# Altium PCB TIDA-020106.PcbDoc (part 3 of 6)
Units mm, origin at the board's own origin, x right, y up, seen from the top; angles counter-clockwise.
Board outline 158.53 x 83.25 mm, 6 copper layers (Top Layer, GND, Power, Sig4, GND (Mid4), Bottom Layer), stack 1.59 mm thick; 410 components, 255 nets, 1280 pads, 2405 vias.
Unrouted connection lines stored in the file: 294.
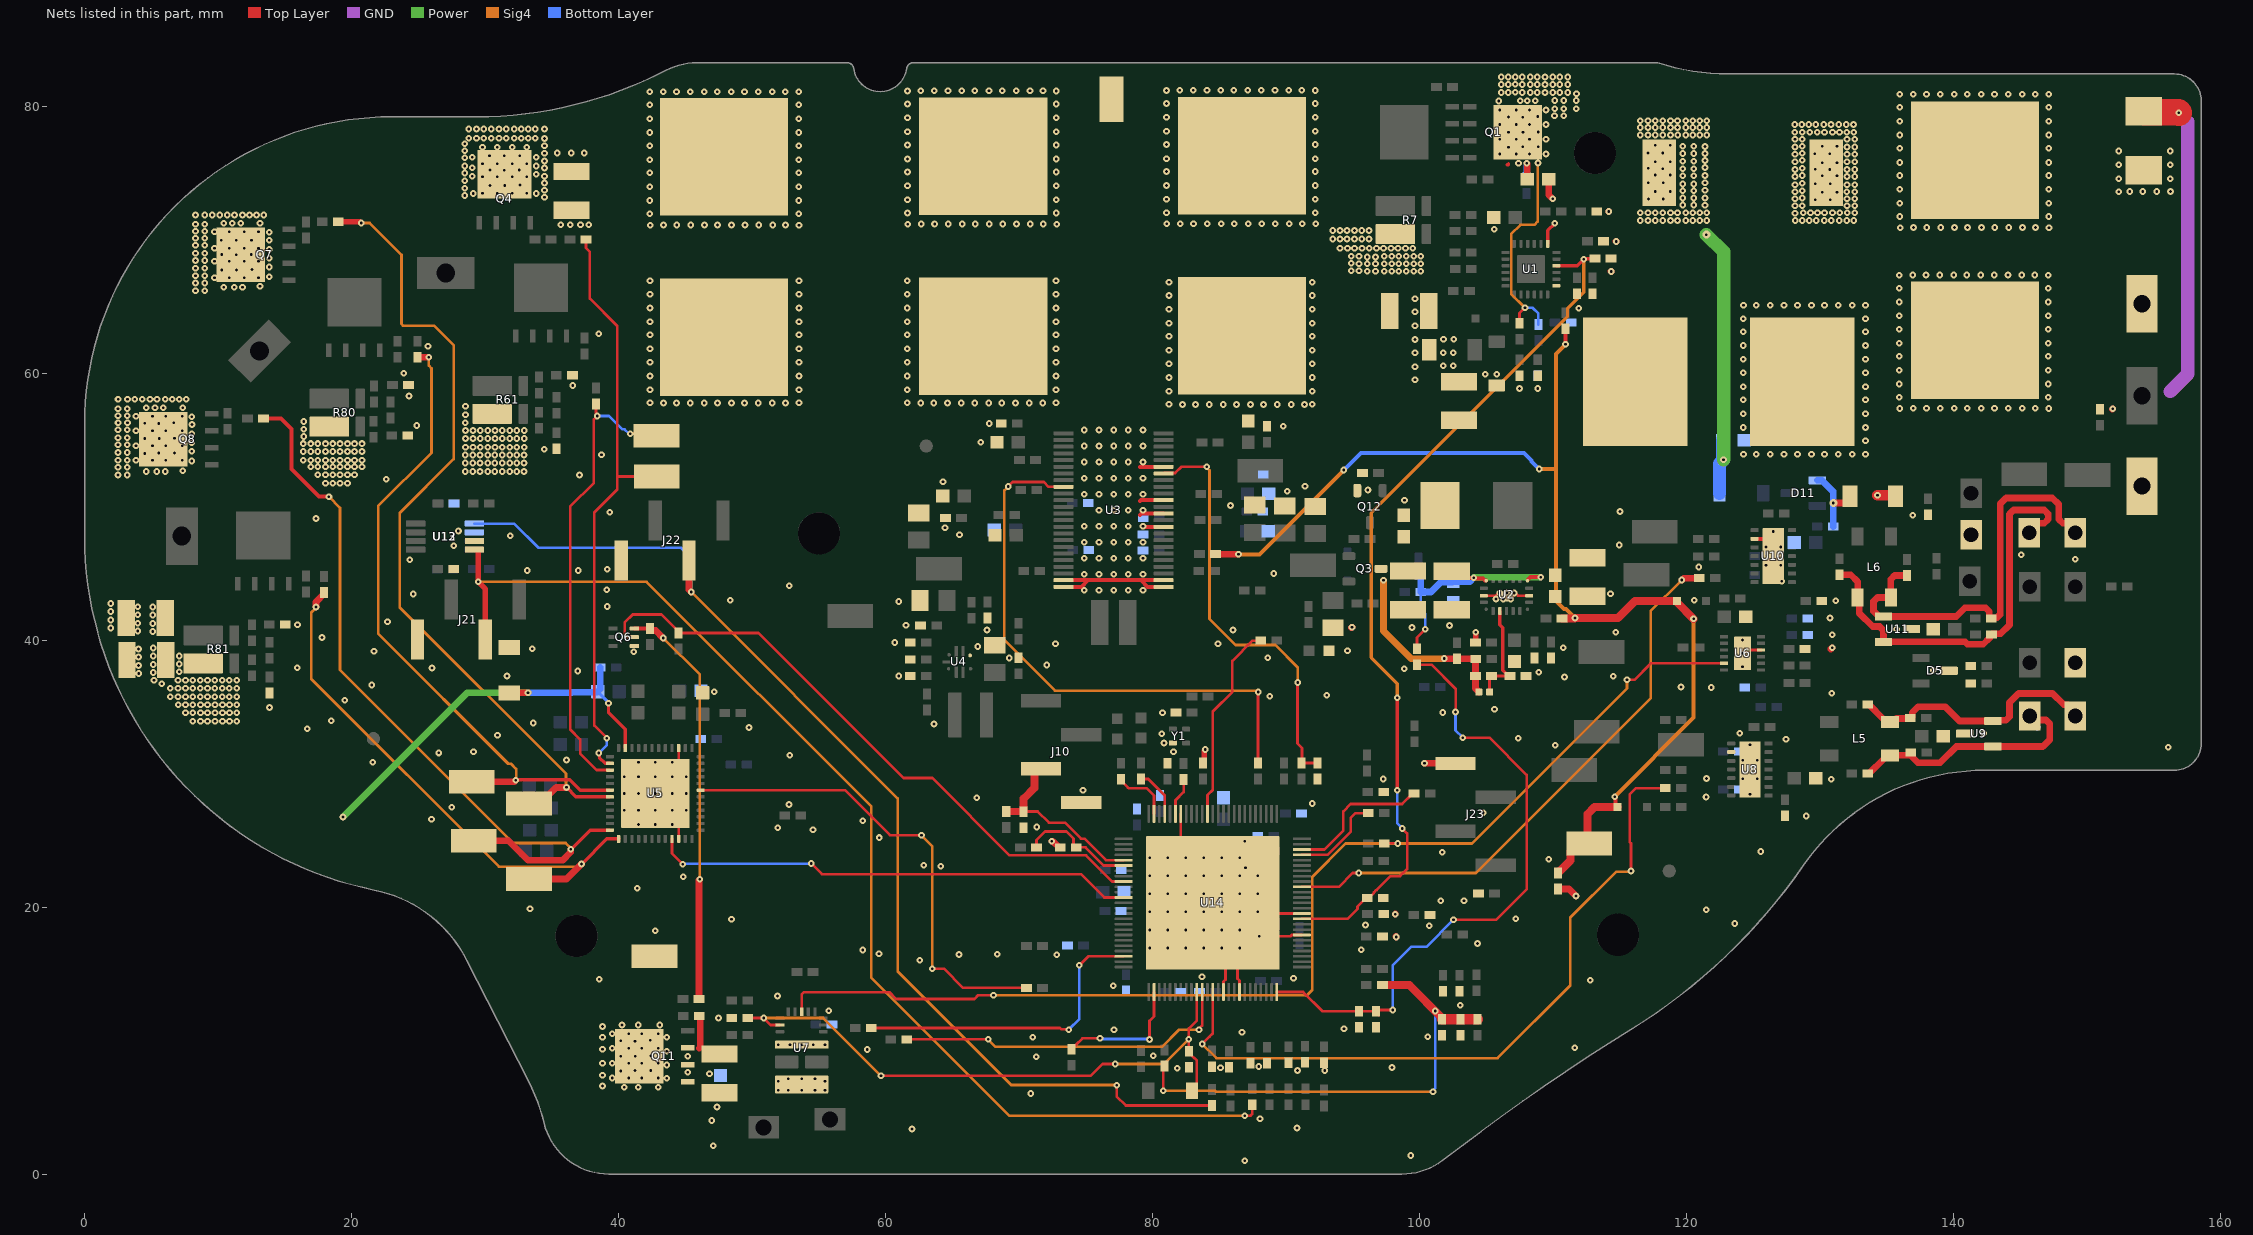
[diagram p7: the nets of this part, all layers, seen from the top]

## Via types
v1: diameter 0.5, hole 0.2, Top Layer to Bottom Layer, 2315 vias
v2: diameter 0.5, hole 0.2, Top Layer to Bottom Layer, tented both sides, 87 vias
v3: diameter 0.6, hole 0.2, Top Layer to Bottom Layer, 3 vias

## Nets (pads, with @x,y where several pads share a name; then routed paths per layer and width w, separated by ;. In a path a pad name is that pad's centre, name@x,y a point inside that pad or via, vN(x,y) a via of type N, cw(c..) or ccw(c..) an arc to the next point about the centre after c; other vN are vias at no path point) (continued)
12V_Cobra: C25.1 C26.2 C30.2 L2.2 Q3.3 R25.2 R32.1 R33.1 | length 13.9
  Top Layer w0.5: v1(101.831,38.624) 101.854,38.601 R32.1@104.019,38.601 ; R32.1@104.182,38.567 104.182,37.32 R33.1@104.177,37.316 104.177,36.37 C30.2@104.432,36.114
  Sig4 w0.5: v1(97.285,44.485) 97.285,40.687 99.349,38.624 ; 99.365,38.607 101.815,38.607 v1(101.831,38.624)
48V/12V_BDC: C96.2 C97.1 Q11.1 Q11.2 Q11.3 R87.1 U7.4 | length 2.5
  Top Layer w0.5: R87.1@46.026,11.849 46.063,11.849 46.113,11.799 46.113,9.508 46.041,9.436
  Bottom Layer w0.2: v1@45.156,7.624 45.158,7.624 v1(45.163,7.628)
  other v1: 45.163,8.83
  other v2: 51.96,9.695 52.835,9.695 53.71,9.695 54.585,9.695 55.46,9.695
48V/12V_C: C16.1 D11.1 R99.2 | length 5.8
  Top Layer w0.5: v3(130.984,50.265) 131.936,50.265 132.236,50.565 C16.1@132.236,50.781 C16.1@132.218,50.799
  Bottom Layer w0.5: D11.1@129.781,51.964 130.131,51.964 130.965,51.13 130.965,50.284 v3(130.984,50.265) 130.984,48.502 R99.2@130.983,48.501
48V/12V_IN: C8.1 D1.2 J3.1 L1.1
  other v1: 135.985,70.892 147.138,70.892 136.985,70.908 137.985,70.908 139.02,70.908 140.058,70.908 141.029,70.908 142.085,70.908 143.085,70.908 144.12,70.908 145.158,70.908 146.129,70.908 128.124,71.433 128.651,71.433 129.18,71.436 129.703,71.433 130.307,71.433 130.838,71.433 131.414,71.433 131.982,71.433 132.523,71.433 135.957,71.733 147.109,71.733 128.117,71.986 128.74,72.003 129.267,72.003 129.797,72.005 130.32,72.003 130.924,72.003 131.455,72.003 132.03,72.003 132.599,72.003 128.11,72.54 128.65,72.543 132,72.54 132.599,72.54 135.957,72.733 147.109,72.733 129.633,72.975 130.739,72.975 128.11,73.067 132,73.067 132.599,73.067 128.65,73.122 130.153,73.546 131.258,73.546 128.107,73.596 131.997,73.596 132.596,73.596 152.356,73.594 153.19,73.6 154.162,73.6 155.2,73.6 156.235,73.6 128.65,73.662 135.957,73.768 147.109,73.768 128.11,74.119 132,74.119 132.599,74.119 129.626,74.186 130.739,74.186 128.65,74.231 152.356,74.562 156.223,74.565 128.11,74.723 132,74.723 132.599,74.723 128.65,74.806 130.153,74.783 131.258,74.783 135.957,74.806 147.109,74.806 128.11,75.254 130.705,75.254 132,75.254 132.599,75.254 129.626,75.273 128.65,75.337 152.356,75.6 156.223,75.6 130.153,75.767 131.258,75.767 135.957,75.778 147.109,75.778 128.11,75.83 132,75.83 132.599,75.83 128.65,75.941 128.11,76.398 132,76.398 132.599,76.398 129.601,76.42 130.705,76.42 128.653,76.464 152.356,76.635 156.223,76.638 135.957,76.833 147.109,76.833 128.11,76.938 132,76.938 132.599,76.938 128.65,76.994 130.153,77.003 131.258,77.003 128.11,77.517 128.65,77.521 132,77.517 132.599,77.517 135.957,77.833 147.109,77.833 128.104,78.041 128.645,78.041 129.213,78.041 129.789,78.041 130.32,78.041 130.924,78.041 131.447,78.038 131.976,78.041 132.503,78.041 128.093,78.623 128.62,78.623 129.149,78.626 129.672,78.623 130.277,78.623 130.808,78.623 131.383,78.623 131.951,78.623 132.492,78.623 135.957,78.868 147.109,78.868 135.957,79.906 147.109,79.906 135.957,80.878 147.109,80.878 136.957,80.894 137.957,80.894 138.992,80.894 140.029,80.894 141.001,80.894 142.057,80.894 143.057,80.894 144.092,80.894 145.129,80.894 146.101,80.894
48V/12V_IN_FILTERED: C9.2 C10.2 D3.2 L1.2 Q1.5 R12.2 R13.2 R153.1 | length 40.3
  Top Layer w0.2: R12.2@107.48,63.736 107.48,64.496 v1(107.881,64.896)
  Top Layer w0.25: 106.554,75.614 106.632,75.614 106.654,75.635 106.654,75.706
  Top Layer w0.5: v1(108.013,75.721) 108.059,75.676 C10.2@108.059,74.515
  Top Layer w1: Q1.5@107.281,77.863 Q1.5@107.459,78.041
  Power w1: v3(121.473,70.374) 122.768,69.079 122.768,53.529 v1(122.753,53.514)
  Sig4 w0.2: v1(107.881,64.896) 106.852,65.925 106.852,70.419 107.541,71.108 108.599,71.108 108.84,71.349 108.84,75.719 v1(108.859,75.738)
  Bottom Layer w0.2: v1(107.881,64.896) 108.454,64.896 108.886,64.465 R13.2@108.886,63.641
  Bottom Layer w0.5: R153.1@108.013,74.659 R153.1@108.013,74.808 ; R153.1@108.013,74.809 v1(108.013,75.721)
  Bottom Layer w1: D3.2@122.454,50.999 122.454,53.215 v1(122.753,53.514) 122.712,53.555 C9.2@122.712,54.963
  other v1: 116.52,71.433 117.099,71.433 117.639,71.433 118.208,71.433 118.783,71.433 119.314,71.433 119.918,71.433 120.441,71.43 120.971,71.433 121.498,71.433 116.52,72.005 117.099,72.005 117.639,72.005 118.208,72.005 118.783,72.005 119.314,72.005 119.918,72.005 120.441,72.003 120.971,72.005 121.498,72.005 119.7,72.591 120.523,72.591 121.369,72.581 117.135,73.037 118.242,73.037 119.7,73.118 120.523,73.118 121.369,73.122 117.656,73.608 118.761,73.608 119.697,73.648 120.52,73.648 121.369,73.69 119.7,74.171 120.523,74.171 117.129,74.249 118.242,74.249 121.369,74.266 119.7,74.775 120.523,74.775 121.369,74.797 117.656,74.845 118.761,74.845 119.7,75.306 120.523,75.306 117.129,75.335 118.208,75.316 121.369,75.401 107.4,75.731 117.656,75.829 118.761,75.829 119.7,75.881 120.523,75.881 121.372,75.924 106.004,76.406 107.241,76.406 108.225,76.406 109.462,76.406 119.7,76.45 120.523,76.45 121.369,76.453 117.103,76.482 118.208,76.482 106.645,76.925 107.713,76.959 108.878,76.959 119.7,76.99 120.523,76.99 121.369,76.98 117.656,77.066 118.761,77.066 106.004,77.511 107.241,77.511 108.225,77.511 109.462,77.511 116.527,77.833 117.106,77.833 117.646,77.833 118.215,77.833 118.79,77.833 119.321,77.833 119.925,77.833 120.448,77.83 120.978,77.833 121.505,77.833 106.645,78.038 107.731,78.038 108.878,78.064 116.52,78.399 117.099,78.399 117.639,78.399 118.208,78.399 118.783,78.399 119.314,78.399 119.918,78.399 120.441,78.396 120.971,78.399 121.498,78.399 106.004,78.628 107.241,78.628 108.225,78.628 109.462,78.628 116.52,78.913 117.099,78.913 117.639,78.913 118.208,78.913 118.783,78.913 119.314,78.913 119.918,78.913 120.441,78.91 120.971,78.913 121.498,78.913 107.713,79.164 106.645,79.182 108.84,79.217 110.102,79.287 110.792,79.287 106.004,79.706 107.241,79.706 108.225,79.706 109.462,79.706 110.105,79.809 110.795,79.809 111.736,79.809 105.927,80.388 107.536,80.409 108.059,80.406 108.663,80.406 110.105,80.414 110.795,80.414 111.736,80.414 111.739,80.937 106.1,81.024 106.627,81.024 107.157,81.027 107.679,81.024 108.284,81.024 108.815,81.024 109.39,81.024 109.958,81.024 110.499,81.024 111.077,81.024 106.1,81.623 106.627,81.623 107.157,81.626 107.679,81.623 108.284,81.623 108.815,81.623 109.39,81.623 109.958,81.623 110.499,81.623 111.077,81.623 106.1,82.179 106.627,82.179 107.157,82.181 107.679,82.179 108.284,82.179 108.815,82.179 109.39,82.179 109.958,82.179 110.499,82.179 111.077,82.179
48V/12V_P: C5.1 C6.1 C21.1 C22.1 C23.2 C24.2 C28.1 C60.1 C61.1 C67.2 C68.1 C73.1 C74.1 C75.1 C76.1 Q4.5 Q7.5 Q8.5 Q11.5 R7.1 R22.2 R27.1 R58.2 R127.2 TP1.1 U2.11 U2.17 U5.35 | length 50.7
  Top Layer w0.2: R127.2@99.798,39.359 99.798,40.195 v1(100.42,40.817)
  Top Layer w0.25: v1(39.233,35.268) 39.233,34.589 40.493,33.329 U5.35@40.493,31.915
  Top Layer w0.3: C22.1@102.402,45.165 102.9,44.667 v1(104.038,44.667) 104.076,44.629 104.73,44.629 104.909,44.45 U2.17@104.983,44.45 ; 108.158,44.587 108.286,44.715 v1(109.061,44.715)
  Top Layer w0.5: C68.1@31.813,36.063 v1(33.213,36.063)
  Power w0.5: v1(19.351,26.751) 28.663,36.063 v1(33.213,36.063) ; v1(104.038,44.667) 104.086,44.715 v1(109.061,44.715)
  Bottom Layer w0.2: R22.2@100.078,43.601 100.078,42.28 100.42,41.938 v1(100.42,40.817)
  Bottom Layer w0.25: C67.2@38.433,36.143 39.185,35.391 39.185,35.316 v1(39.233,35.268)
  Bottom Layer w0.5: v1(33.213,36.063) 36.484,36.063 36.524,36.103 38.393,36.103 C67.2@38.433,36.143 38.612,36.322 R58.2@38.612,37.959 ; R27.1@99.9,44.914 99.9,44.855 100.078,44.677 R22.2@100.078,43.601 100.852,43.601 101.591,44.339 102.441,44.339 102.467,44.366 103.737,44.366 v1(104.038,44.667)
  other v1: 40.421,6.505 41.456,6.505 42.96,6.504 38.788,6.599 43.593,7.178 39.516,7.205 40.753,7.205 41.737,7.205 42.974,7.205 38.788,7.41 40.157,7.724 41.225,7.758 42.391,7.758 43.593,8.178 38.788,8.31 39.516,8.31 40.753,8.31 41.737,8.31 42.974,8.31 40.157,8.837 41.243,8.837 42.391,8.863 43.593,9.213 38.788,9.345 39.516,9.428 40.753,9.428 41.737,9.428 42.974,9.428 40.157,9.981 41.225,9.963 42.352,10.016 38.788,10.251 43.593,10.251 39.516,10.505 40.753,10.505 41.737,10.505 42.974,10.505 38.788,11.061 40.249,11.164 41.456,11.164 43.068,11.17 4.046,37.499 4.035,38.095 4.035,38.733 4.035,39.332 3.987,40.677 1.957,40.91 3.976,41.273 1.946,41.506 3.976,41.911 1.946,42.144 3.976,42.51 1.946,42.743 2.5,52.365 3.2,52.365 4.616,52.627 5.396,52.627 6.028,52.627 7.335,52.693 2.5,52.944 3.2,52.944 8.022,53.417 3.849,53.465 5.086,53.465 6.07,53.465 7.306,53.465 2.5,53.484 3.2,53.484 4.489,53.984 5.557,54.017 6.723,54.017 2.5,54.052 3.2,54.052 8.022,54.139 3.849,54.57 5.086,54.57 6.07,54.57 7.306,54.57 2.5,54.628 3.2,54.628 8.022,54.789 4.489,55.096 5.576,55.096 6.723,55.122 2.5,55.159 3.2,55.159 8.022,55.452 3.849,55.687 5.086,55.687 6.07,55.687 7.306,55.687 2.5,55.763 3.2,55.763 8.034,56.145 5.557,56.222 4.489,56.241 2.503,56.286 3.203,56.286 6.684,56.275 8.022,56.741 3.849,56.765 5.086,56.765 6.07,56.765 7.306,56.765 2.5,56.815 3.2,56.815 2.5,57.342 3.2,57.342 4.616,57.403 5.885,57.403 7.335,57.403 5.266,57.412 2.503,58.03 3.208,58.033 3.748,58.033 4.317,58.033 4.892,58.033 5.423,58.033 6.028,58.033 6.55,58.03 7.08,58.033 7.607,58.033 8.296,66.177 8.996,66.177 10.412,66.439 11.193,66.439 11.824,66.439 13.131,66.504 8.296,66.755 8.996,66.755 9.72,67.141 10.825,67.141 11.942,67.141 13.02,67.141 13.818,67.229 8.296,67.295 8.996,67.295 96.073,67.625 96.688,67.625 97.35,67.631 97.907,67.631 98.428,67.631 98.992,67.631 99.545,67.631 100.079,67.631 94.875,67.668 95.451,67.658 10.273,67.725 11.377,67.725 12.53,67.763 8.296,67.864 8.996,67.864 13.818,67.951 95.451,68.193 96.073,68.182 96.688,68.182 97.35,68.191 97.907,68.191 98.428,68.191 98.992,68.191 99.545,68.191 100.079,68.191 94.875,68.225 9.72,68.378 10.825,68.378 11.942,68.378 13.02,68.378 8.296,68.439 8.996,68.439 13.818,68.601 96.073,68.703 96.688,68.703 94.875,68.745 95.451,68.745 97.35,68.745 97.907,68.745 98.428,68.745 98.992,68.745 99.545,68.745 100.079,68.745 11.351,68.872 10.273,68.89 12.477,68.89 8.296,68.97 8.996,68.97 13.818,69.264 9.72,69.362 10.825,69.362 11.942,69.362 13.02,69.362 94.032,69.355 94.589,69.355 95.11,69.355 95.674,69.355 96.227,69.355 96.761,69.355 97.293,69.355 97.85,69.355 98.371,69.355 98.935,69.355 99.488,69.355 8.296,69.575 8.996,69.575 10.239,69.958 11.351,69.958 12.496,69.958 13.83,69.957 93.475,70.048 94.032,70.048 94.552,70.048 95.117,70.048 95.67,70.048 96.204,70.048 8.299,70.097 8.999,70.097 13.818,70.553 9.72,70.599 10.825,70.599 11.942,70.599 13.02,70.599 8.296,70.627 8.996,70.627 93.475,70.686 94.032,70.686 94.552,70.686 95.117,70.686 95.67,70.686 96.204,70.686 42.355,71.084 53.508,71.084 43.355,71.1 44.355,71.1 45.39,71.1 46.428,71.1 47.4,71.1 48.455,71.1 49.455,71.1 50.49,71.1 51.528,71.1 52.5,71.1 61.662,71.148 72.815,71.148 8.296,71.154 8.996,71.154 62.662,71.164 63.662,71.164 64.697,71.164 65.735,71.164 66.707,71.164 67.762,71.164 68.762,71.164 69.797,71.164 70.835,71.164 71.807,71.164 81.057,71.183 82.057,71.199 83.057,71.199 84.092,71.199 85.129,71.199 86.101,71.199 87.157,71.199 88.157,71.199 89.192,71.199 90.229,71.199 91.201,71.199 92.209,71.183 10.412,71.215 11.063,71.223 11.681,71.215 13.131,71.215 8.299,71.842 9.004,71.845 9.545,71.845 10.113,71.845 10.689,71.845 11.22,71.845 11.824,71.845 12.347,71.842 12.876,71.845 13.403,71.845 42.327,71.925 53.48,71.925 61.634,71.989 72.787,71.989 81.029,72.024 92.181,72.024 42.327,72.925 53.48,72.925 61.634,72.989 72.787,72.989 81.029,73.024 92.181,73.024 34.443,73.178 28.471,73.303 29.103,73.45 33.813,73.45 29.803,73.469 30.908,73.469 32.026,73.469 33.103,73.469 34.443,73.705 28.471,73.843 42.327,73.96 53.48,73.96 61.634,74.024 72.787,74.024 30.356,74.053 31.461,74.053 81.029,74.059 92.181,74.059 32.614,74.091 34.44,74.234 28.471,74.412 29.803,74.706 30.908,74.706 32.026,74.706 33.103,74.706 29.037,74.757 34.443,74.757 33.813,74.9 28.471,74.987 42.327,74.998 53.48,74.998 61.634,75.062 72.787,75.062 81.029,75.096 92.181,75.096 31.435,75.2 30.356,75.219 32.561,75.219 34.443,75.361 29.037,75.388 28.471,75.518 33.822,75.518 29.803,75.69 30.908,75.69 32.026,75.69 33.103,75.69 34.443,75.892 42.327,75.97 53.48,75.97 61.634,76.034 72.787,76.034 81.029,76.068 92.181,76.068 28.471,76.122 29.037,76.169 33.813,76.169 30.322,76.286 31.435,76.286 32.579,76.286 34.443,76.468 35.402,76.489 36.457,76.489 37.429,76.489 28.474,76.645 29.803,76.927 30.908,76.927 32.026,76.927 33.103,76.927 34.443,77.036 42.327,77.025 53.48,77.025 61.634,77.089 72.787,77.089 81.029,77.124 92.181,77.124 28.471,77.175 28.775,77.585 29.354,77.585 29.894,77.585 30.462,77.585 31.038,77.585 31.569,77.585 32.173,77.585 32.696,77.582 33.225,77.585 33.752,77.585 34.443,77.577 42.327,78.025 53.48,78.025 61.634,78.089 72.787,78.089 81.029,78.124 92.181,78.124 28.775,78.285 29.354,78.285 29.894,78.285 30.462,78.285 31.038,78.285 31.569,78.285 32.173,78.285 32.696,78.282 33.225,78.285 33.752,78.285 34.44,78.282 42.327,79.06 53.48,79.06 61.634,79.124 72.787,79.124 81.029,79.159 92.181,79.159 42.327,80.098 53.48,80.098 61.634,80.162 72.787,80.162 81.029,80.196 92.181,80.196 42.327,81.07 53.48,81.07 43.327,81.086 44.327,81.086 45.362,81.086 46.4,81.086 47.372,81.086 48.427,81.086 49.427,81.086 50.462,81.086 51.5,81.086 52.472,81.086 61.634,81.134 62.634,81.15 63.634,81.15 64.669,81.15 65.707,81.15 66.679,81.15 67.734,81.15 68.734,81.15 69.769,81.15 70.807,81.15 71.779,81.15 72.787,81.134 81.029,81.168 92.181,81.168 82.029,81.184 83.029,81.184 84.064,81.184 85.101,81.184 86.073,81.184 87.129,81.184 88.129,81.184 89.164,81.184 90.201,81.184 91.173,81.184
BOOT1: J10.3 R147.2 R149.2 U14.80 | length 13.9
  Top Layer w0.2: R149.2@70.336,27.162 71.379,27.162 72.219,26.322 73.44,26.322 74.634,25.128 74.886,25.128 76.497,23.517 U14.80@77.827,23.517
  Top Layer w0.5: R147.2@69.031,27.162 69.035,27.157 70.331,27.157 R149.2@70.336,27.153
  Top Layer w0.6: R149.2@70.336,27.162 70.336,28.122 71.149,28.935 J10.3@71.149,30.375
BOOT2: R148.2 R150.2 U14.81 | length 8.7
  Top Layer w0.2: R148.2@71.295,24.482 71.295,25.029 71.931,25.665 73.531,25.665 74.068,25.128 74.068,24.682 R150.2@74.269,24.482 ; R150.2@74.269,24.482 74.966,24.482 76.331,23.117 U14.81@77.827,23.117
CAN1H: J17.1 L5.2 R98.1 R100.2 U9.2 | length 19.9
  Top Layer w0.5: R98.1@133.551,35.17 133.651,35.17 134.756,34.065 135.026,34.065 L5.2@135.226,33.865 135.451,33.865 135.716,34.13 136.697,34.13 R100.2@136.747,34.18 136.847,34.18 136.897,34.23 136.897,34.57 137.344,35.017 139.353,35.017 140.433,33.937 U9.2@142.933,33.937 142.983,33.987 143.901,33.987 144.175,34.262 144.175,35.323 144.859,36.007 147.404,36.007 148.25,35.161 148.55,35.161 149.1,34.611 J17.1@149.1,34.311 ; J17.1@149.2,34.011 J17.1@149.2,34.311
CAN1L: J18.1 L5.1 R103.1 R105.1 U9.1 | length 19.3
  Top Layer w0.5: R105.1@133.551,29.997 133.651,29.997 134.801,31.147 134.801,31.165 135.001,31.365 L5.1@135.226,31.365 R103.1@136.876,31.365 ; R103.1@136.876,31.515 136.926,31.515 136.926,31.201 137.312,30.815 138.975,30.815 140.197,32.037 U9.1@142.933,32.037 146.679,32.037 147.2,32.558 147.2,33.73 146.907,34.023 J18.1@145.7,34.023
  Bottom Layer w0.5: J18.1@145.7,34.311 145.7,34.011 J18.1@146.25,33.461
CAN2H: J19.1 L6.2 R109.1 R110.2 U11.1 | length 31.6
  Top Layer w0.5: R109.1@136.492,44.84 135.577,44.84 135.284,44.547 135.284,43.211 L6.2@135.301,43.193 134.285,43.193 133.992,42.901 133.992,42.167 134.392,41.767 U11.1@134.742,41.767 140.188,41.767 140.841,42.421 142.375,42.421 142.668,42.128 142.668,41.684 142.718,41.634 R110.2@142.818,41.634 142.868,41.684 143.253,41.684 143.475,41.906 143.475,50.199 143.924,50.648 147.381,50.648 147.875,50.153 147.875,49.043 148.168,48.75 148.65,48.75 149.2,48.2 J19.1@149.2,47.9
CAN2L: J20.1 L6.1 R113.1 R115.1 U11.2 | length 31.3
  Top Layer w0.5: R115.1@131.455,44.892 132.291,44.892 132.801,44.382 L6.1@132.801,43.193 132.919,43.076 132.919,42.034 133.936,41.017 134.449,41.017 134.742,40.724 U11.2@134.742,39.867 140.858,39.867 141.039,39.686 142.211,39.686 142.675,40.15 142.675,40.386 142.725,40.436 R113.1@142.825,40.436 142.875,40.486 143.525,40.486 144.175,41.136 144.175,49.439 144.486,49.75 146.777,49.75 147.071,49.457 147.071,49.043 146.778,48.75 146.3,48.75 145.75,48.2 J20.1@145.75,47.9
CLK_DRV3263: R143.1 U5.19 | length 35.9
  Top Layer w0.2: U5.19@46.143,28.765 56.949,28.765 60.323,25.391 v1(62.676,25.391) ; v1(63.495,15.392) 64.352,15.392 65.785,13.958 R143.1@70.549,13.958
  Sig4 w0.2: v1(62.676,25.391) 62.676,25.347 63.495,24.528 v1(63.495,15.392)
CLK_PMIC: R142.2 U3.33 | length 42.1
  Top Layer w0.2: v1(69.173,51.502) 69.512,51.84 71.854,51.84 72.208,51.485 U3.33@73.324,51.485 ; R142.2@87.882,30.797 87.882,36.194 v1@87.902,36.214
  Sig4 w0.2: v1(69.173,51.502) 68.884,51.212 68.884,40.014 72.683,36.214 v1@87.902,36.214
  other v1: 87.902,36.114
CLKEPB: R135.1 U6.11 U7.13 | length 87.4
  Top Layer w0.2: U7.13@53.71,12.17 53.71,13.465 53.876,13.631 60.268,13.631 60.777,13.122 66.636,13.122 66.914,13.399 v1(68.08,13.399) ; R135.1@97.35,24.782 98.338,24.782 v1(98.355,24.765) ; v1(115.521,37.029) 116.076,37.029 117.306,38.259 U6.11@122.791,38.259
  Sig4 w0.2: v1(68.08,13.399) 91.571,13.399 91.952,13.781 91.952,22.273 94.445,24.765 v1(98.355,24.765) 103.9,24.765 115.521,36.386 v1(115.521,37.029)
COS_P1: J21.2 R121.1 U12.1 | length 90
  Top Layer w0.2: v1(86.899,4.365) 86.917,4.383 87.34,4.383 87.457,4.5 R121.1@87.457,5.2
  Top Layer w0.4: U12.1@29.2,46.775 29.465,46.775 29.49,46.75 v1(29.49,44.369) 29.49,44.342 30.01,43.822 J21.2@30.01,40.043
  Sig4 w0.2: v1(29.49,44.369) 42.095,44.369 58.92,27.544 58.92,14.703 69.258,4.365 v1(86.899,4.365)
COS_P2: J22.2 R125.1 U13.1 | length 85.3
  Top Layer w0.2: v1(77.301,6.654) 77.301,5.828 77.984,5.145 R125.1@84.456,5.145
  Top Layer w0.5: J22.2@45.272,45.963 45.272,43.771 v1(45.441,43.603)
  Sig4 w0.2: v1(45.441,43.603) 60.892,28.152 60.892,15.196 69.406,6.682 77.273,6.682 v1(77.301,6.654)
  Bottom Layer w0.2: U13.1@29.189,48.727 32.17,48.727 33.977,46.919 44.664,46.919 45.441,46.143 v1(45.441,43.603)
CUTOFF_ASCIN: Q6.2 R53.1 U14.84 | length 47.7
  Top Layer w0.2: Q6.2@41.175,40.216 40.611,40.216 40.45,40.377 40.45,41.316 41.054,41.92 43.212,41.92 44.494,40.638 R53.1@44.494,40.538 50.465,40.538 61.328,29.675 63.495,29.675 69.288,23.882 75,23.882 76.965,21.917 U14.84@77.827,21.917
Cutoff_EPB: Q6.3 R57.1 R85.1 | length 30.7
  Top Layer w0.3: Q6.3@41.175,40.866 R57.1@42.34,40.866
  Top Layer w0.5: R57.1@42.34,40.866 42.34,40.766 42.39,40.716 42.772,40.716 v1(43.329,40.159) ; R85.1@46.018,13.122 46.018,22.02 v1(46.077,22.079)
  Sig4 w0.2: v1(43.329,40.159) 46.077,37.412 v1(46.077,22.079)
DC_BUS: C115.1 R127.1 R132.2 U14.25 | length 47.4
  Top Layer w0.2: U14.25@89.302,13.642 91.267,13.642 92.709,12.2 C115.1@95.449,12.2 R132.2@96.739,12.2 ; R132.2@96.939,11.9 96.739,12.1 96.936,12.297 v1(97.969,12.297) ; R127.1@99.798,38.159 100.893,38.159 102.694,36.357 102.694,34.616 v1(102.687,34.609) ; v1(102.536,19.057) 105.741,19.057 108.015,21.332 108.015,29.91 105.232,32.693 v1(103.227,32.693)
  Bottom Layer w0.2: v1(97.969,12.297) 97.969,15.633 99.365,17.03 100.508,17.03 v1(102.536,19.057) ; v1(102.687,34.609) 102.687,33.233 v1(103.227,32.693)
DRVOFF_DRV3263: U5.9 U14.87 | length 36.3
  Top Layer w0.2: U5.9@43.993,25.115 43.993,24.023 v1(44.794,23.222) ; v1(54.429,23.267) 55.223,22.473 74.621,22.473 76.377,20.717 U14.87@77.827,20.717
  Bottom Layer w0.2: v1(44.794,23.222) 44.817,23.245 54.406,23.245 v1(54.429,23.267)
DRVOFF_EPB: R90.1 U14.2 | length 10
  Top Layer w0.2: R90.1@73.919,9.354 73.919,9.454 74.119,9.654 74.219,9.654 74.736,10.171 v1(76.052,10.171) ; v1(79.762,10.08) 79.762,11.48 80.102,11.82 U14.2@80.102,13.642
  Bottom Layer w0.2: v1(76.052,10.171) 76.103,10.12 79.722,10.12 v1(79.762,10.08)
EN_CAN1: R107.1 U14.13 | length 54.2
  Top Layer w0.2: v1(83.701,9.751) 84.262,10.312 84.502,10.552 U14.13@84.502,13.642 ; v1(115.827,22.706) 115.827,24.779 115.727,24.879 115.727,28.428 116.207,28.908 R107.1@118.393,28.908
  Sig4 w0.2: v1(83.701,9.751) 84.77,8.682 105.824,8.682 111.276,14.135 111.276,19.208 114.727,22.658 115.779,22.658 v1(115.827,22.706)
EN_CAN2: R117.1 U14.41 | length 43.2
  Top Layer w0.2: U14.41@91.177,21.517 93.938,21.517 94.975,22.554 v1(95.441,22.554)
  Top Layer w0.5: v1(119.637,44.506) 119.768,44.637 R117.1@120.936,44.637
  Sig4 w0.2: v1(95.441,22.554) 104.216,22.554 117.3,35.638 117.3,42.169 v1(119.637,44.506)
F29H85x_25MHZ_CLK: R137.2 U14.70 | length 2.9
  Top Layer w0.2: U14.70@81.702,26.992 81.702,28.005 82.316,28.62 R137.2@82.316,29.558 ; R137.2@82.458,29.558 R137.2@82.458,29.602
FB: C30.1 R33.2 R35.2 U2.3 | length 7.8
  Top Layer w0.25: C30.1@105.232,36.114 105.232,37.171 R33.2@105.377,37.316 R35.2@106.758,37.316 ; U2.3@106.002,42.181 106.002,41.154 106.227,40.929 106.227,37.747 R35.2@106.658,37.316
FORCE_SENSOR_SENT: C1.2 R1.1 R3.2 R128.2 R145.2 | length 36.6
  Top Layer w0.2: v1@80.798,6.155 v1(80.798,6.255) 80.798,7.99 R145.2@80.902,8.095 ; C1.2@101.681,11.6 C1.2@101.681,11.7
  Top Layer w0.6: R128.2@97.208,14.163 99.218,14.163 C1.2@101.681,11.7
  Top Layer w0.8: C1.2@101.681,11.6 102.281,11.6 R3.2@104.342,11.6
  Sig4 w0.2: v1(80.798,6.255) 84.652,6.255 84.727,6.18 v1(100.994,6.18)
  Bottom Layer w0.2: v1(100.994,6.18) 100.994,6.261 101.162,6.428 v1(101.162,12.219)
GHA: R50.2 TP10.1 U5.38 | length 45.1
  Top Layer w0.2: R50.2@37.556,70.011 37.556,69.365 37.834,69.087 37.834,65.573 39.893,63.515 39.893,52.289 ; v1(39.109,32.661) 39.109,32.664 38.177,33.596 38.177,49.577 39.893,51.293 39.893,52.289 ; TP10.1@42.847,52.26 39.922,52.26 39.893,52.289
  Top Layer w0.25: v1(38.512,31.543) 38.56,31.495 38.56,31.193 38.988,30.765 U5.38@39.343,30.765
  Bottom Layer w0.2: v1(38.512,31.543) 39.109,32.14 v1(39.109,32.661)
GHB: R66.2 TP12.1 U5.43 | length 62.3
  Top Layer w0.25: v1(36.094,28.967) 36.796,28.265 U5.43@39.343,28.265
  Top Layer w0.4: R66.2@18.997,71.338 20.598,71.338 20.693,71.243 v1(20.721,71.243)
  Top Layer w0.5: TP12.1@33.288,27.765 34.113,27.765 35.315,28.967 v1(36.094,28.967)
  Sig4 w0.2: v1(20.721,71.243) 21.345,71.243 23.73,68.858 23.73,63.676 23.847,63.559 26.173,63.559 27.64,62.092 27.64,53.552 23.6,49.513 23.6,42.443 36.05,29.993 36.05,29.011 v1(36.094,28.967)
GHC: R67.2 TP13.1 U5.48 | length 57.2
  Top Layer w0.25: v1(36.41,24.343) 36.447,24.343 37.869,25.765 U5.48@39.343,25.765
  Top Layer w0.3: R67.2@13.4,56.594 14.698,56.594 15.491,55.802 15.491,52.808 17.552,50.746 v1(18.295,50.746)
  Top Layer w0.5: TP13.1@29.137,24.965 31.762,24.965 33.227,23.5 35.794,23.5 36.41,24.117 v1(36.41,24.343)
  Sig4 w0.2: v1(18.295,50.746) 19.128,49.913 19.128,37.777 32.098,24.806 36.028,24.806 36.41,24.424 v1(36.41,24.343)
GLA: R55.2 TP11.1 U5.39 | length 35.2
  Top Layer w0.2: R55.2@38.299,57.684 38.299,56.97 38.399,56.87 v1(38.399,56.789) 38.399,56.78 38.141,56.522 38.141,51.778 36.361,49.999 36.361,33.322 37.111,32.572 37.111,31.494 38.34,30.265 U5.39@39.343,30.265 ; v1(40.862,55.465) 42.688,55.465 TP11.1@42.843,55.31
  Bottom Layer w0.2: v1(38.399,56.789) 39.273,56.789 40.27,55.792 40.453,55.792 40.78,55.465 v1(40.862,55.465)
GLB: R72.2 TP14.1 U5.42 | length 49.5
  Top Layer w0.2: R72.2@24.942,61.081 R72.2@24.942,61.181
  Top Layer w0.25: v1(32.281,29.496) 32.327,29.542 36.332,29.542 37.109,28.765 U5.42@39.343,28.765
  Top Layer w0.5: R72.2@24.942,61.181 25.759,61.181 v1(25.776,61.199) ; TP14.1@28.996,29.384 32.17,29.384 v1(32.281,29.496)
  Sig4 w0.2: v1(25.776,61.199) 25.776,60.568 25.984,60.36 25.984,54.033 21.988,50.037 21.988,40.48 31.728,30.74 31.925,30.74 32.318,30.348 32.318,29.532 v1(32.281,29.496)
GLC: R73.2 TP15.1 U5.1 | length 41
  Top Layer w0.25: v1(37.219,23.226) 39.108,25.115 U5.1@39.993,25.115
  Top Layer w0.5: v1(17.33,42.481) 17.33,42.86 17.939,43.469 R73.2@17.939,43.569 ; TP15.1@33.288,22.1 36.097,22.1 37.219,23.222 v1(37.219,23.226)
  Sig4 w0.2: v1(17.33,42.481) 17.33,42.417 16.971,42.058 16.971,37.092 17.332,36.732 31.038,23.026 36.788,23.026 36.793,23.031 36.943,23.031 37.138,23.226 v1(37.219,23.226)
GND: C1.1 C2.2 C3.1 C4.2 C5.2 C6.2 C7.1 C8.2 C9.1 C10.1 C12.1 C15.2 C16.2 C17.2 C18.2 C19.2 C21.2 C22.2 C23.1 C24.1 C25.2 C26.1 C27.2 C28.2 C29.1 C31.2 C32.2 C33.2 C34.2 C35.2 C36.2 C37.1 C40.2 C41.2 C42.2 C43.1 C44.1 C45.1 C46.1 C47.1 C48.2 C49.2 C50.2 C51.2 C52.2 C53.1 C54.1 C55.2 C56.2 C57.2 C58.1 C59.1 C60.2 C61.2 C62.2 C64.1 C68.2 C70.2 C71.2 C73.2 C74.2 C75.2 C76.2 C78.2 C79.2 C80.2 C83.2 C84.2 C85.2 C86.2 C87.2 C88.1 C89.1 C90.1 C91.1 C92.1 C93.1 C94.1 C95.2 C96.1 C97.2 C98.1 C99.1 C100.1 C101.2 C102.2 C103.2 C104.1 C105.2 C106.2 C107.2 C108.1 C109.2 C110.2 C111.2 C112.2 C113.2 C114.2 C115.2 C116.2 C117.2 C118.1 C120.2 C121.2 C122.2 C123.2 C124.2 C125.2 C126.2 C127.2 C128.2 C129.2 C130.2 C131.2 C132.2 C133.2 C134.2 C135.2 C136.2 C137.2 C138.1 C139.2 C140.2 C141.2 C142.2 C143.2 C144.2 C145.2 C146.2 C147.2 C148.1 D1.1 D4.2 D5.3 D10.2 J4.1 J10.4 J13.1 J16.1 J21.4 J22.4 J23.4 Q6.1 Q12.2 R1.2 R2.1 R14.1 R17.1 R18.1 R20.1 R21.1 R29.1 R30.2 R34.1 R35.1 R47.1 R48.2 R49.1 R61.1 R80.1 R81.1 R95.1 R104.2 R114.2 R131.1 R132.1 R136.2 R146.2 R149.1 R150.1 R155.2 R156.2 TP2.1 U1.7 U1.13 U2.9 U2.19 U2.21 U3.1 U3.2 U3.10 U3.12 U3.14 U3.19 U3.47 U3.48 U4.4 U5.10 U5.27 U5.49 U6.4 U6.13 U7.6 U8.2 U8.15 U9.3 U10.2 U10.15 U11.3 U12.2 U13.2 U14.15 U14.18 U14.32 U14.36 U14.69 U14.101 Y1.2 | length 102.5
  Top Layer w0.2: U5.10@44.493,25.115 44.493,26.765 v2(44.003,27.255) v2(42.743,28.515) v2(44.003,29.775) 44.493,30.265 U5.27@44.493,31.915 ; U14.69@82.102,26.992 82.102,22.717 v2(82.477,22.342) v2(83.827,20.992) U14.101@84.502,20.317 v2(85.177,19.642) U14.101@85.302,19.517 ; U14.15@85.302,13.642 85.302,14.412 85.452,14.563 U14.101@85.452,19.367 ; U14.18@86.502,13.642 86.502,14.49 86.352,14.64 86.352,18.467 U14.101@85.452,19.367 ; v2(86.527,18.292) 87.003,17.816 90.306,17.816 90.407,17.917 U14.32@91.177,17.917 ; U14.36@91.177,19.517 U14.101@85.302,19.517 ; U2.19@104.802,43.331 105.706,43.331 105.906,43.531 v1(105.987,43.531) ; v1(106.537,43.531) U2.21@106.788,43.28 ; U2.21@106.812,43.28 107.015,43.28 ; v1(107.087,43.531) 107.168,43.531 107.368,43.331 U2.9@108.202,43.331 ; U14.101@85.302,19.517 U14.101@85.452,19.367
  Top Layer w0.25: U1.13@109.586,69.689 109.586,70.686 110.105,71.206 v1(110.105,71.227) ; v2(124.181,39.009) 124.431,39.259 U6.4@125.571,39.259
  Top Layer w0.3: U3.48@73.324,43.985 74.668,43.985 75.168,44.485 ; U3.47@73.324,44.485 75.168,44.485 ; 79.064,49.377 79.173,49.485 U3.12@80.824,49.485 ; 79.064,50.433 79.117,50.485 U3.14@80.824,50.485 ; 79.064,52.985 U3.19@80.824,52.985 ; v1(79.274,48.535) 79.328,48.535 79.378,48.485 U3.10@80.824,48.485 ; U3.1@80.824,43.985 79.623,43.985 79.123,44.485 ; U3.2@80.824,44.485 79.123,44.485 ; U10.2@125.089,47.59 125.839,47.59 126.489,46.94 U10.15@126.489,46.29 ; 75.168,44.485 79.123,44.485
  Top Layer w0.4: v1@24.26,58.319 v1(24.295,58.284) ; R146.2@83.771,30.802 83.871,30.902 83.871,31.717 83.936,31.782 v1(83.936,31.809) ; R34.1@104.177,39.807 104.186,39.816 104.186,40.585 v1(104.195,40.593)
  Top Layer w0.5: C64.1@46.293,36.053 C64.1@46.368,36.128 ; v1(72.45,24.928) 72.523,24.928 72.969,24.482 R150.1@73.069,24.482 ; J10.4@74.149,27.835 74.535,27.835 J10.4@74.785,28.085 ; C121.2@81.735,34.57 C121.2@81.74,34.575 ; v1@94.89,40.927 v1(94.925,40.961) ; C148.1@97.263,20.67 C148.1@97.279,20.655 ; R131.1@97.279,19.516 R131.1@97.295,19.501 ; v1@98.17,19.501 98.179,19.491 v1(98.179,19.465) ; v1@98.219,17.8 v1(98.251,17.767) ; C25.2@99.125,42.274 C25.2@99.18,42.22 ; v1(100.361,30.767) 102.687,30.767 J23.4@102.694,30.76 ; C118.1@100.719,19.35 C118.1@100.766,19.396 ; C7.1@105.553,71.658 C7.1@105.581,71.63 ; C10.1@109.659,74.515 109.659,73.365 109.96,73.063 v1(109.96,73.051) ; R156.2@110.362,21.36 111.188,21.36 v1(111.709,20.838) ; v1@114.15,72.122 v1(114.169,72.102) ; v1@114.335,67.631 114.352,67.614 v1(114.357,67.614) ; v1@114.699,69.877 v1(114.718,69.858) ; v1@130.797,39.337 v1(130.893,39.433) ; v1@151.884,57.302 v1(151.919,57.337)
  Top Layer w0.8: v1(134.285,50.844) 135.572,50.844 C16.2@135.636,50.781
  Top Layer w1: C56.2@62.49,42.896 C56.2@62.561,42.967
  Top Layer w2: D1.1@154.229,79.61 154.309,79.53 156.823,79.53 v1(156.853,79.5)
  GND w1: 156.223,58.621 157.533,59.93 157.533,78.821 v1(156.853,79.5)
  other v1: 86.899,0.997 99.326,1.392 47.079,2.121 61.966,3.379 90.811,3.454 46.968,4.021 88.037,4.137 47.36,5.03 70.857,6.041 46.799,7.519 90.847,7.762 92.883,7.762 81.838,7.929 85.077,7.96 97.931,7.99 87.953,8.068 71.271,8.795 80.043,8.876 58.614,9.338 111.61,9.467 71.021,10.26 100.593,10.29 86.683,10.639 77.104,10.815 94.328,10.896 47.472,11.694 55.729,12.23 103.036,12.651 51.894,13.342 77.052,14.117 112.763,14.515 38.549,14.586 90.552,14.684 83.698,14.776 62.561,16.023 72.822,16.426 65.49,16.448 68.346,16.472 59.501,16.518 58.282,16.789 95.625,16.816 104.332,17.273 87.992,17.816 42.743,18.222 100.719,18.595 95.946,18.661 123.587,18.771 48.446,19.095 107.199,19.14 121.454,19.797 33.355,19.882 101.568,20.465 103.324,20.465 41.392,21.405 44.835,22.273 86.951,22.941 64.117,23.073 62.843,23.139 109.678,23.575 101.696,24.102 125.536,24.16 86.899,24.923 59.514,25.209 54.557,25.784 51.909,25.957 71.312,26.008 58.273,26.467 25.985,26.572 128.95,26.824 104.767,27.063 27.507,27.488 52.754,27.692 91.952,27.767 66.821,28.187 121.451,28.251 124.736,28.458 74.785,28.752 130.83,29.575 97.263,29.597 124.186,29.618 125.286,29.618 121.486,29.637 21.588,30.84 124.186,30.998 125.286,30.998 36.097,31.023 52.813,31.375 26.511,31.551 29.13,31.63 81.552,31.639 156.065,31.977 110.151,32.117 124.736,32.158 80.848,32.294 127.439,32.586 107.388,32.658 30.919,32.87 80.678,32.99 123.972,33.015 142.225,33.015 16.664,33.353 49.761,33.458 63.62,33.713 33.6,33.792 8.101,33.92 8.671,33.92 9.206,33.92 9.758,33.92 10.323,33.92 10.843,33.92 11.401,33.92 18.47,33.966 7.558,34.558 8.101,34.558 8.671,34.558 9.206,34.558 9.758,34.558 10.323,34.558 10.843,34.558 11.401,34.558 80.731,34.57 101.724,34.578 105.602,34.829 13.847,34.954 7.001,35.157 7.558,35.157 8.101,35.157 8.671,35.157 9.206,35.157 9.758,35.157 10.323,35.157 10.843,35.157 11.401,35.157 19.487,35.495 6.409,35.761 6.99,35.753 7.547,35.753 8.09,35.753 8.66,35.753 9.195,35.753 9.747,35.753 10.312,35.753 10.832,35.753 11.39,35.753 88.766,35.805 93.03,35.859 130.857,36.015 47.168,36.128 6.409,36.391 6.99,36.391 7.547,36.391 8.09,36.391 8.66,36.391 9.195,36.391 9.747,36.391 10.312,36.391 10.832,36.391 11.39,36.391 121.838,36.444 119.575,36.487 21.501,36.642 5.771,36.737 5.189,36.99 6.99,36.99 7.547,36.99 8.09,36.99 8.66,36.99 9.195,36.99 9.747,36.99 10.312,36.99 10.832,36.99 11.39,36.99 110.84,37.233 114.499,37.283 31.637,37.317 60.982,37.317 5.147,37.574 108.928,37.585 7.083,37.635 36.943,37.693 138.468,37.732 98.843,37.859 26.02,37.909 15.928,37.937 72.056,38.142 5.136,38.17 7.08,38.209 69.249,38.657 88.619,38.671 5.136,38.808 7.08,38.808 41.132,39.116 21.671,39.156 94.585,39.202 33.528,39.344 5.136,39.407 110.757,39.434 66.891,39.525 72.718,39.733 84.897,39.733 60.671,39.817 17.776,40.198 130.893,40.393 114.679,40.59 5.107,40.65 67.593,40.763 86.018,40.762 135.716,40.817 99.419,40.941 102.226,41.094 61.523,41.111 15.944,41.157 5.096,41.246 22.687,41.385 130.738,41.656 5.096,41.884 5.096,42.483 39.137,42.52 60.982,42.896 131.159,42.941 120.565,42.977 48.365,42.985 105.712,43.081 106.262,43.081 106.812,43.081 24.616,43.451 114.29,43.462 74.874,43.735 75.974,43.735 77.074,43.735 78.174,43.735 79.274,43.735 39.109,43.765 52.77,44.072 127.129,44.419 74.874,44.935 75.974,44.935 77.074,44.935 78.174,44.935 79.274,44.935 89.056,44.985 33.161,45.214 36.966,45.214 39.137,45.312 120.911,45.477 125.939,45.6 127.039,45.6 24.35,46.022 149.1,46.066 74.874,46.135 75.974,46.135 77.074,46.135 78.174,46.135 79.274,46.135 145.06,46.391 125.939,46.98 127.039,46.98 27.639,47.061 114.945,47.125 74.874,47.335 75.974,47.335 77.074,47.335 78.174,47.335 79.274,47.335 31.882,47.817 65.526,47.896 126.489,48.14 27.995,48.174 64.444,48.417 74.874,48.535 75.974,48.535 77.074,48.535 78.174,48.535 17.33,49.103 136.926,49.351 39.329,49.577 115,49.632 75.974,49.735 77.074,49.735 78.174,49.735 79.274,49.735 85.827,50.085 98.855,50.485 74.874,50.935 75.974,50.935 77.074,50.935 78.174,50.935 79.274,50.935 90.082,51.155 96.121,51.247 91.404,51.517 18.041,51.74 18.575,51.74 19.128,51.74 19.692,51.74 64.291,51.86 22.583,52.051 74.874,52.135 75.974,52.135 77.074,52.135 78.174,52.135 79.274,52.135 17.47,52.378 18.041,52.378 18.575,52.378 19.128,52.378 19.692,52.378 20.213,52.378 37.067,52.365 28.512,52.627 29.069,52.627 29.612,52.627 30.182,52.627 30.717,52.627 31.269,52.627 31.834,52.627 32.354,52.627 32.912,52.627 16.927,52.977 17.47,52.977 18.041,52.977 18.575,52.977 19.128,52.977 19.692,52.977 20.213,52.977 20.77,52.977 28.512,53.265 29.069,53.265 29.612,53.265 30.182,53.265 30.717,53.265 31.269,53.265 31.834,53.265 32.354,53.265 32.912,53.265 74.874,53.335 75.974,53.335 77.074,53.335 78.174,53.335 79.274,53.335 16.37,53.484 16.927,53.484 17.47,53.484 18.041,53.484 18.575,53.484 19.128,53.484 19.692,53.484 20.213,53.484 20.77,53.484 28.512,53.864 29.069,53.864 29.612,53.864 30.182,53.864 30.717,53.864 31.269,53.864 31.834,53.864 32.354,53.864 32.912,53.864 38.718,53.894 124.248,53.929 125.22,53.929 126.257,53.929 127.292,53.929 128.292,53.929 129.348,53.929 130.32,53.929 131.357,53.929 132.392,53.929 133.392,53.929 16.37,54.122 16.927,54.122 17.47,54.122 18.041,54.122 18.575,54.122 19.128,54.122 19.692,54.122 20.213,54.122 20.77,54.122 34.418,54.29 28.526,54.458 29.084,54.458 29.626,54.458 30.197,54.458 30.731,54.458 31.284,54.458 31.848,54.458 32.369,54.458 32.926,54.458 74.874,54.535 75.974,54.535 77.074,54.535 78.174,54.535 79.274,54.535 16.37,54.721 16.927,54.721 17.47,54.721 18.041,54.721 18.575,54.721 19.128,54.721 19.692,54.721 20.213,54.721 20.77,54.721 67.118,54.81 133.392,54.929 28.526,55.096 29.084,55.096 29.626,55.096 30.197,55.096 30.731,55.096 31.284,55.096 31.848,55.096 32.369,55.096 32.926,55.096 16.403,55.257 28.526,55.695 29.084,55.695 29.626,55.695 30.197,55.695 30.731,55.695 31.284,55.695 31.848,55.695 32.369,55.695 32.926,55.695 74.874,55.735 75.974,55.735 77.074,55.735 78.174,55.735 79.274,55.735 16.403,55.8 124.232,55.929 133.392,55.929 89.777,56.01 24.879,56.073 67.767,56.225 28.51,56.292 16.403,56.371 28.524,56.887 124.232,56.964 133.392,56.964 135.957,57.345 147.109,57.345 136.957,57.361 137.957,57.361 138.992,57.361 140.029,57.361 141.001,57.361 142.057,57.361 143.057,57.361 144.092,57.361 145.129,57.361 146.101,57.361 28.524,57.525 82.228,57.647 83.2,57.647 84.238,57.647 85.273,57.647 86.273,57.647 87.328,57.647 88.3,57.647 89.338,57.647 90.373,57.647 91.373,57.647 81.22,57.663 91.953,57.663 43.355,57.755 44.327,57.755 45.365,57.755 46.4,57.755 47.4,57.755 48.455,57.755 49.427,57.755 50.465,57.755 51.5,57.755 52.5,57.755 62.616,57.755 63.588,57.755 64.626,57.755 65.661,57.755 66.661,57.755 67.716,57.755 68.688,57.755 69.726,57.755 70.761,57.755 71.761,57.755 42.347,57.771 53.5,57.771 61.608,57.771 72.761,57.771 124.232,58.001 133.392,58.001 135.929,58.186 147.081,58.186 81.22,58.635 91.953,58.635 42.347,58.743 53.5,58.743 61.608,58.743 72.761,58.743 107.48,58.842 108.842,58.842 124.232,58.973 133.392,58.973 36.57,59.073 135.929,59.186 147.081,59.186 99.653,59.496 81.22,59.673 91.953,59.673 42.347,59.781 53.5,59.781 61.608,59.781 72.761,59.781 104.918,59.922 105.778,59.922 23.889,59.978 124.232,60.029 133.392,60.029 135.929,60.221 147.081,60.221 99.653,60.467 101.768,60.551 102.523,60.551 81.22,60.708 91.953,60.708 42.347,60.816 53.5,60.816 61.608,60.816 72.761,60.816 124.232,61.029 133.392,61.029 135.929,61.258 147.081,61.258 99.653,61.523 101.768,61.523 102.523,61.523 81.22,61.708 91.953,61.708 42.347,61.816 53.5,61.816 61.608,61.816 72.761,61.816 25.722,62.008 124.232,62.064 133.392,62.064 135.929,62.23 147.081,62.23 99.653,62.523 101.784,62.531 102.539,62.531 81.22,62.763 91.953,62.763 42.347,62.871 53.5,62.871 61.608,62.871 72.761,62.871 38.498,62.959 124.232,63.101 133.392,63.101 135.929,63.286 147.081,63.286 99.653,63.558 81.22,63.735 91.953,63.735 42.347,63.843 53.5,63.843 61.608,63.843 72.761,63.843 124.232,64.073 133.392,64.073 135.929,64.286 147.081,64.286 99.653,64.596 81.22,64.773 91.953,64.773 111.917,64.851 42.347,64.881 53.5,64.881 61.608,64.881 72.761,64.881 124.248,65.081 125.22,65.081 126.257,65.081 127.292,65.081 128.292,65.081 129.348,65.081 130.32,65.081 131.357,65.081 132.392,65.081 133.392,65.081 135.929,65.321 147.081,65.321 99.653,65.567 81.22,65.808 91.953,65.808 42.347,65.916 53.5,65.916 61.608,65.916 72.761,65.916 135.929,66.358 147.081,66.358 81.22,66.808 91.953,66.808 42.347,66.916 53.5,66.916 61.608,66.916 72.761,66.916 135.929,67.33 147.081,67.33 136.929,67.346 137.929,67.346 138.964,67.346 140.001,67.346 140.973,67.346 142.029,67.346 143.029,67.346 144.064,67.346 145.101,67.346 146.073,67.346 105.581,70.77 35.656,71.117 36.373,71.117 37.135,71.117 37.768,71.117
  other v2: 51.96,6.295 52.71,6.295 53.71,6.295 54.71,6.295 55.46,6.295 51.96,6.945 55.46,6.945 52.71,7.145 53.71,7.145 54.71,7.145 79.777,16.942 81.127,16.942 82.477,16.942 83.827,16.942 85.177,16.942 86.527,16.942 79.777,18.292 81.127,18.292 82.477,18.292 83.827,18.292 85.177,18.292 79.777,19.642 81.127,19.642 82.477,19.642 83.827,19.642 86.527,19.642 87.877,19.642 79.777,20.992 81.127,20.992 82.477,20.992 85.177,20.992 86.527,20.992 87.877,20.992 79.777,22.342 81.127,22.342 83.827,22.342 85.177,22.342 86.527,22.342 87.877,22.342 79.777,23.692 81.127,23.692 82.477,23.692 83.827,23.692 85.177,23.692 86.527,23.692 41.483,26.19 42.743,26.19 44.003,26.19 40.418,27.255 41.483,27.255 42.743,27.255 45.068,27.255 40.418,28.515 41.483,28.515 44.003,28.515 45.068,28.515 40.418,29.775 41.483,29.775 42.743,29.775 45.068,29.775 41.483,30.84 42.743,30.84 44.003,30.84 124.181,38.009 124.181,40.009
IMON_LM74930: C148.2 R18.2 U1.10 U14.35 | length 66.1
  Top Layer w0.2: U14.35@91.177,19.117 94.585,19.117 95.338,19.87 95.338,20.045 95.963,20.67 96.163,20.67 96.563,21.07 96.563,21.095 96.739,21.27 96.763,21.27 97.811,22.317 98.521,22.317 99.062,22.858 99.062,25.517 v1(98.686,25.892)
  Top Layer w0.25: v1(98.312,28.752) v1(98.312,35.681) ; U1.10@110.236,68.039 111.813,68.039 112.327,68.553 113.1,68.553 R18.2@113.135,68.589
  Sig4 w0.25: v1(98.312,35.681) 98.312,36.747 96.363,38.695 96.363,49.522 111.066,64.225 111.066,64.813 112.292,66.039 v1(112.292,68.518)
  Bottom Layer w0.2: v1(98.312,28.752) 98.312,26.296 98.686,25.921 v1(98.686,25.892)
IN1_EPB: R94.1 U14.98 | length 23.6
  Top Layer w0.2: R94.1@58.92,10.947 73.052,10.947 73.152,10.847 73.67,10.847 v1(73.702,10.815) ; v1(74.501,15.647) 75.171,16.317 U14.98@77.827,16.317
  Bottom Layer w0.2: v1(73.702,10.815) 74.501,11.614 v1(74.501,15.647)
IN2_EPB: R93.1 U14.11 | length 25.7
  Top Layer w0.2: R93.1@61.49,10.093 v1(67.671,10.093) ; v1(83.467,10.815) 83.467,10.896 83.702,11.131 U14.11@83.702,13.642
  Sig4 w0.2: v1(67.671,10.093) 68.234,9.53 80.682,9.53 81.967,10.815 v1(83.467,10.815)
INH_CAN: D6.1 D7.1 R19.1 R26.1 R36.1 R156.1 TP19.1 | length 87.9
  Top Layer w0.3: v1(110.919,62.15) R19.1@110.919,63.312 ; v1(114.613,28.275) 114.613,28.221 114.666,28.167 114.666,27.65 D6.1@114.816,27.5
  Top Layer w0.5: R36.1@84.709,46.441 86.412,46.441 v1(86.425,46.428)
  Top Layer w0.6: R156.1@110.362,22.56 110.362,22.66 110.462,22.66 111.295,23.492 111.295,24.176 111.884,24.765 TP19.1@112.697,24.765 112.56,24.903 112.56,26.962 113.098,27.5 D6.1@114.816,27.5 ; R26.1@110.661,41.634 111.614,41.634 v1(111.636,41.656) 114.851,41.656 116.116,42.922 D7.1@119.254,42.922 119.254,42.851 v1(120.515,41.591)
  Sig4 w0.3: v1(86.425,46.428) 88.009,46.428 v1(94.318,52.736) ; v1(108.945,52.816) 110.196,52.816 ; v1(110.919,62.15) 110.196,61.427 110.196,52.816 ; v1(111.636,41.656) 110.974,42.318 110.819,42.318 110.196,42.941 110.196,52.816 ; v1(114.613,28.275) 114.613,28.292 120.515,34.194 v1(120.515,41.591)
  Bottom Layer w0.3: v1(94.318,52.736) 95.59,54.008 107.822,54.008 108.379,53.452 108.379,53.382 v1(108.945,52.816)
Isense_EPB: C100.2 D12.2 R95.2 U7.2 U14.10 | length 45.5
  Top Layer w0.2: R95.2@49.669,11.694 v1(50.857,11.694) 51.381,11.17 U7.2@52.085,11.17 ; v1(59.653,7.359) 75.355,7.359 76.249,8.253 v1(77.202,8.253) ; D12.2@82.94,6.255 83.297,6.612 83.297,7.465 83.303,7.471 83.303,8.519 83.127,8.695 83.103,8.695 82.703,9.095 C100.2@82.703,9.195 82.708,9.201 v1(82.708,10.114) 82.708,10.902 83.302,11.496 U14.10@83.302,13.642
  Sig4 w0.2: v1(50.857,11.694) 55.318,11.694 v1(59.653,7.359) ; v1(77.202,8.253) 80.848,8.253 v1(82.708,10.114)
LED1: R152.2 U14.72 | length 3.7
  Top Layer w0.2: R152.2@79.123,29.593 79.667,29.593 80.902,28.357 U14.72@80.902,26.992
LED2: R151.2 U14.74 | length 4.4
  Top Layer w0.2: R151.2@77.631,29.573 77.631,29.473 78.15,28.953 78.152,28.953 78.212,28.893 79.561,28.893 80.102,28.352 U14.74@80.102,26.992
MCU_ERRORSTS: R134.1 R136.1 U3.18 | length 31.6
  Top Layer w0.2: U3.18@80.824,52.485 80.857,52.518 81.686,52.518 82.154,52.985 v1(84.058,52.985) ; v1(90.856,36.828) 90.847,36.819 90.847,32.257 91.186,31.918 91.186,30.839 R134.1@91.144,30.797 R136.1@92.357,30.797
  Sig4 w0.2: v1(84.058,52.985) 84.058,52.917 84.257,52.718 84.257,41.595 86.212,39.64 89.183,39.64 90.856,37.967 v1(90.856,36.828)
MCU_TCK: R139.1 U14.48 | length 11
  Top Layer w0.2: U14.48@91.177,24.317 92.863,24.317 94.274,25.729 94.274,27.168 94.827,27.721 98.686,27.721 99.479,28.513 R139.1@99.579,28.513
MCU_TMS: R138.1 U14.47 | length 7
  Top Layer w0.2: U14.47@91.177,23.917 93.106,23.917 94.836,25.647 94.827,25.657 94.827,26.687 95.178,27.039 R138.1@96.15,27.039 ; R138.1@96.069,26.914 R138.1@96.146,26.837
MOS_LM68645: R154.2 U14.64 | length 15
  Top Layer w0.2: U14.64@84.102,26.992 84.102,28.384 84.497,28.779 84.497,34.65 85.969,36.122 85.969,38.44 87.484,39.955 R154.2@88.103,39.955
